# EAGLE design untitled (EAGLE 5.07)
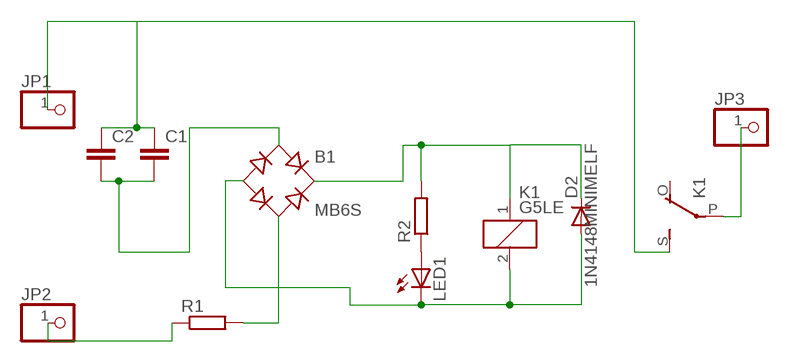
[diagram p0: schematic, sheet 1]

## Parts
B1  MB6S  [SOIC-4]
C1  C-EU102-043X133  [C102-043X133]
C2  C-EU102-043X133  [C102-043X133]
D2  1N4148MINIMELF  [MINIMELF]
JP1  PINHD-1X11MM6  [1X1MM8]
JP2  PINHD-1X11MM6  [1X1MM8]
JP3  PINHD-1X11MM6  [1X1MM8]
K1  G5LE  [G5LE]
LED1  LEDSMT1206  [1206]
R1  R-EU_0309/10  [0309/10]
R2  R-EU_R0805  [R0805]

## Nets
AC1: C1.1 C2.1 JP1.1 K1.S(2:S)
ACOUT: JP3.1 K1.P(2:P)
MINUS: B1.- D2.A K1.2 LED1.C
N$1: LED1.A R2.1
N$10: JP2.1 R1.1
PLUS: B1.+ D2.C K1.1 R2.2
RAC1: B1.~1(AC1) C1.2 C2.2
RAC2: B1.~2(AC2) R1.2
Unconnected: K1.O(2:O)

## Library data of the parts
B1 = rectifier:MB*S: Bridge Rectifier Source: http://www.fairchildsemi.com/ds/MB/MB6S.pdf
C1 C2 = rcl:C-EU: CAPACITOR, European symbol
D2 = diode-1:1N4148: DIODE
JP1-JP3 = pinhead:PINHD-1X1: PIN HEADER
K1 = relay:G5LE: RELAY 1 x switch, 10 A/120 V AC, 8 A/30 V DC, Omron
LED1 = led:LED: LED
R1 R2 = rcl:R-EU_: RESISTOR, European symbol

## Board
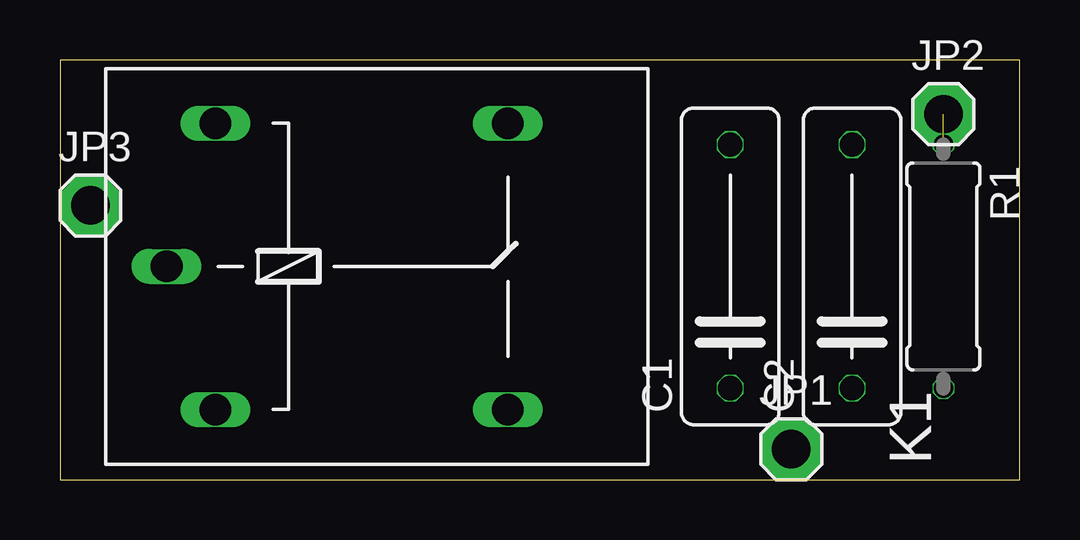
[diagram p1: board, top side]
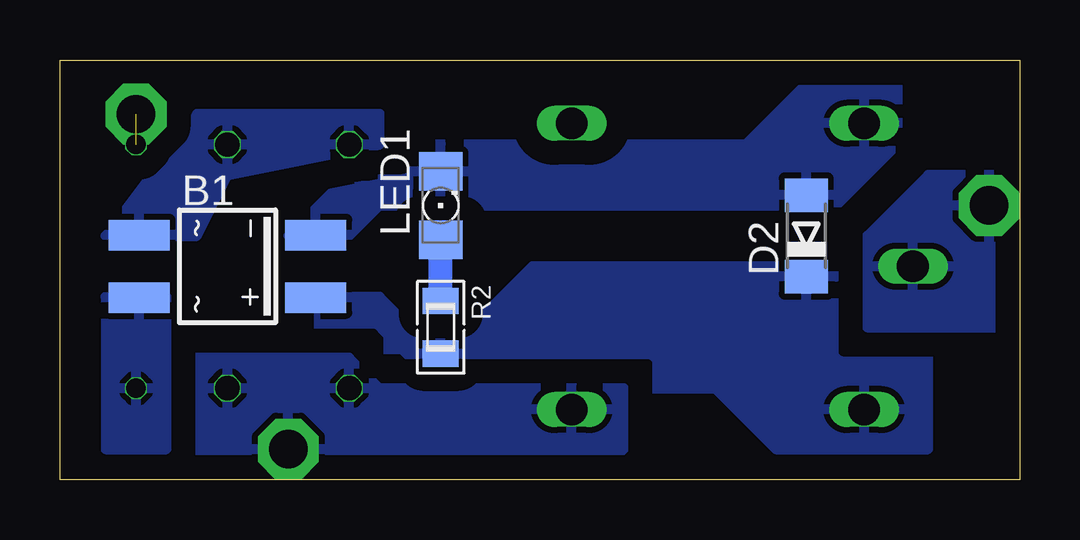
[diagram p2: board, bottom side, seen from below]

Size 40 x 17.5 mm. Coordinates in mm from the lower left corner, seen from the top.
Outline: 0,0 40,0 40,17.5 0,17.5 0,0
Copper layers (1*16): Top 0.035mm / dielectric 1.5mm / Bottom 0.035mm
Design rules "default": minimum track width 10mil, minimum drill 20mil, track to track 8mil, track to pad 8mil, pad to pad 8mil, via to via 8mil, smd to smd 8mil, copper to edge 40mil, drill to drill 8mil, minimum pad ring 1mil, minimum via ring 8mil, stop-mask expansion 4mil, vias tented up to drill 0mil, thermal gap 10mil

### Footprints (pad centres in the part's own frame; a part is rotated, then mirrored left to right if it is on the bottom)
SOIC-4 = smd 1.27 x 2.54: + 1.3,3.685; - -1.3,3.685; ~1 -1.3,-3.685; ~2 1.3,-3.685
C102-043X133 = drill 1.016 octagon: 1 -5.08,0; 2 5.08,0
MINIMELF = smd 1.4 x 1.8: A 1.7,0; C -1.7,0
1X1MM8 = drill 1.6 pad 2.54 octagon: 1 0,0
G5LE = drill 1.321 long: 1 -7.493,-5.969; 2 -7.493,5.969; O 4.699,5.969; P -9.525,0; S 4.699,-5.969
1206 = smd 1.6 x 1.803: A -1.422,0; C 1.422,0
0309/10 = drill 0.813 octagon: 1 -5.08,0; 2 5.08,0
R0805 = smd 1.1 x 1.5: 1 -1.1,0; 2 1.1,0

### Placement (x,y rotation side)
B1  33.02,8.89 270 bottom
C1  27.94,8.89 90 top
C2  33.02,8.89 90 top
D2  8.89,10.16 90 bottom
JP1  30.48,1.27 0 top
JP2  36.83,15.24 0 top
JP3  1.27,11.43 0 top
K1  13.97,8.89 0 top
LED1  24.13,11.43 90 bottom
R1  36.83,8.89 270 top
R2  24.13,6.35 270 bottom

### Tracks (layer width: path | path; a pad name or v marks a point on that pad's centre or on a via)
AC1
  pour Bottom (isolate 1, rank 2): 16.51,3.81 26.67,3.81 27.94,5.08 34.29,5.08 34.29,0 17.78,0 16.51,1.27
ACOUT
  pour Bottom (isolate 1): 1.27,12.7 3.81,12.7 6.35,10.16 6.35,6.35 0,6.35 0,12.7
MINUS
  pour Bottom (isolate 1, rank 2): 5.08,16.51 8.89,16.51 11.43,13.97 26.67,13.97 30.48,10.16 27.94,10.16 26.67,11.43 6.35,11.43 5.08,12.7
N$1
  Bottom 1: R2.1 LED1.A
N$10  (1 unrouted)
PLUS
  pour Bottom (isolate 1, rank 3): 3.81,3.81 3.81,5.08 7.62,8.89 20.32,8.89 22.86,6.35 25.4,6.35 26.67,7.62 29.21,7.62 29.21,5.08 26.67,5.08 25.4,3.81 12.7,3.81 10.16,1.27 3.81,1.27
RAC1
  pour Bottom (isolate 1): 26.67,15.24 34.29,15.24 38.1,10.16 34.29,10.16 33.02,12.7 26.67,13.97
RAC2
  pour Bottom: 35.56,7.62 38.1,7.62 38.1,1.27 35.56,1.27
